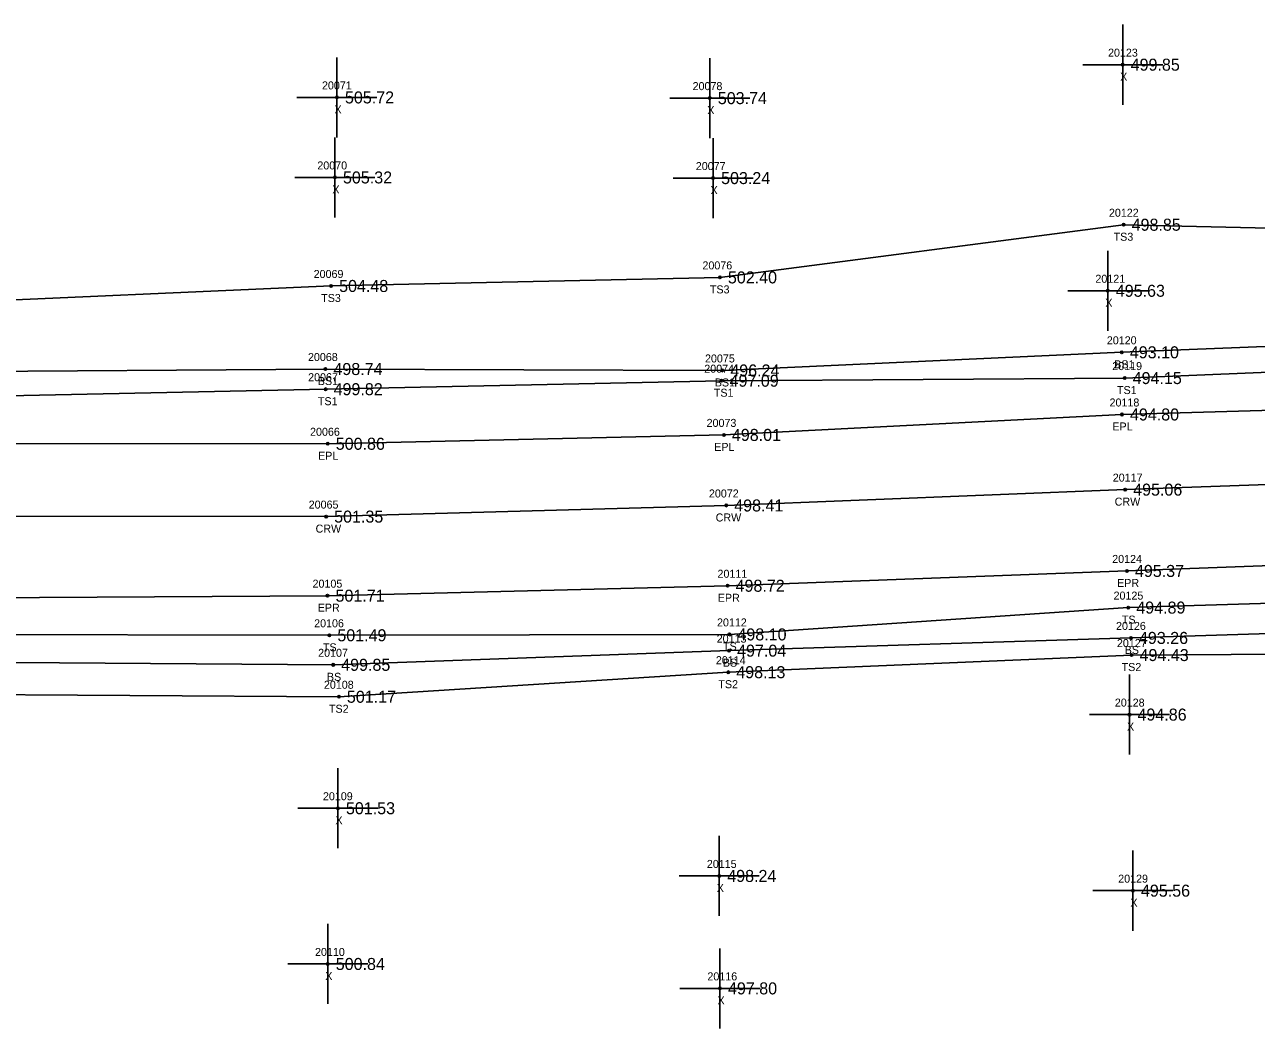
# Model space of a CAD drawing. Extents: x 1785066 to 1786589, y 770293 to 771312.
# Drawn here: x 1785243.3 to 1785397.2, y 770773.1 to 770898.5 of the extents above; entities that cross this region are included whole.
import ezdxf

# ---------------------------------------------------------------- set-up
doc = ezdxf.new("R2010")
doc.units = 0
for name, color, linetype in [('RD_DTM_BkLn1', 7, 'Continuous'), ('RD_DTM_BkLn2', 7, 'Continuous'), ('RD_DTM_BkLn_txCode', 7, 'Continuous'), ('RD_EX_Misc', 7, 'Continuous'), ('RD_EX_Misc_txCode', 7, 'Continuous'), ('RD_EX_Road', 7, 'Continuous'), ('RD_EX_Road_txCode', 7, 'Continuous'), ('RD_EX_TX_Misc_ELEV', 7, 'Continuous'), ('RD_EX_TX_Road_ELEV', 7, 'Continuous'), ('RD_HC_Survey_ELEV', 7, 'Continuous'), ('RD_HC_Survey_txCode', 7, 'Continuous'), ('RD_SMD_Locator', 7, 'Continuous')]:
    doc.layers.add(name, color=color, linetype=linetype)

msp = doc.modelspace()

# ---------------------------------------------------------------- linework, layer by layer
at = {"layer": 'RD_DTM_BkLn1'}
msp.add_lwpolyline([(1785082.06, 770851.29), (1785131.3, 770843.85), (1785181.17, 770839.05), (1785231.06, 770837.12), (1785280.99, 770837.06), (1785330.97, 770838.45), (1785380.81, 770840.43), (1785480.56, 770843.94), (1785580.22, 770847.33), (1785679.99, 770850.66), (1785779.91, 770853.54)], dxfattribs=at)
at = {"layer": 'RD_DTM_BkLn2'}
for points in [[(1785219, 770887.48), (1785221.61, 770869.17), (1785226.44, 770862.44), (1785230.83, 770863.64), (1785281.61, 770865.88), (1785330.18, 770866.95), (1785380.62, 770873.53), (1785481.03, 770871.22), (1785579.17, 770869.06), (1785678.49, 770873.66), (1785753.25, 770880.69), (1785777.57, 770887.66), (1785796.72, 770894.6)], [(1785221.18, 770856.06), (1785231.29, 770855.17), (1785280.9, 770855.5), (1785330.48, 770855.32), (1785380.39, 770857.59), (1785481.4, 770861.59), (1785579.34, 770865.13), (1785679.06, 770868.59), (1785753.94, 770876.35), (1785778.96, 770883.81)], [(1785221.33, 770857.68), (1785219.57, 770857.18), (1785219.95, 770853.94), (1785231.29, 770851.96), (1785280.92, 770852.98), (1785330.39, 770854.04), (1785380.75, 770854.37), (1785480.88, 770858.51), (1785579.51, 770861.16), (1785679.28, 770865.65), (1785754.2, 770872.9), (1785779.7, 770881.19), (1785786.95, 770881.8), (1785789.14, 770878.77), (1785786.05, 770869.32), (1785786.11, 770839.44)], [(1785205.07, 770819.03), (1785219.41, 770822.94), (1785230.95, 770822.33), (1785281.39, 770822.23), (1785331.37, 770822.34), (1785381.2, 770825.69), (1785481.76, 770828.75), (1785580.39, 770831.91), (1785680.81, 770834.37), (1785757.11, 770838.03), (1785775.28, 770836.8), (1785785.27, 770835.59), (1785786.11, 770839.44)], [(1785217.48, 770818.88), (1785230.53, 770818.92), (1785281.87, 770818.54), (1785331.33, 770820.31), (1785381.53, 770821.9), (1785481.77, 770825.03), (1785580.88, 770828.75), (1785679.45, 770830.28), (1785757.48, 770831.63), (1785774.02, 770829.34), (1785791.05, 770829.99), (1785795.95, 770830.77)], [(1785205.07, 770819.03), (1785218.74, 770813.87), (1785230.3, 770814.87), (1785282.58, 770814.55), (1785331.23, 770817.62), (1785381.61, 770819.76), (1785481.26, 770820.42), (1785579.63, 770825.21), (1785679.72, 770826.75), (1785756.33, 770825.6), (1785774.03, 770825.73), (1785791.3, 770827.72), (1785795.65, 770828.98)]]:
    msp.add_lwpolyline(points, dxfattribs=at)
at = {"layer": 'RD_EX_Misc'}
for p, q in [((1785380.5, 770888.53), (1785380.5, 770898.53)), ((1785282.34, 770884.44), (1785282.34, 770894.44)), ((1785328.92, 770884.35), (1785328.92, 770894.35)), ((1785375.5, 770893.53), (1785385.5, 770893.53)), ((1785277.34, 770889.44), (1785287.34, 770889.44)), ((1785323.92, 770889.35), (1785333.92, 770889.35)), ((1785282.09, 770874.44), (1785282.09, 770884.44)), ((1785329.33, 770874.36), (1785329.33, 770884.36)), ((1785277.09, 770879.44), (1785287.09, 770879.44)), ((1785324.33, 770879.36), (1785334.33, 770879.36)), ((1785378.64, 770860.28), (1785378.64, 770870.28)), ((1785373.64, 770865.28), (1785383.64, 770865.28)), ((1785381.35, 770807.32), (1785381.35, 770817.32)), ((1785376.35, 770812.32), (1785386.35, 770812.32)), ((1785282.46, 770795.62), (1785282.46, 770805.62)), ((1785277.46, 770800.62), (1785287.46, 770800.62)), ((1785330.1, 770787.16), (1785330.1, 770797.16)), ((1785381.78, 770785.32), (1785381.78, 770795.32)), ((1785325.1, 770792.16), (1785335.1, 770792.16)), ((1785376.78, 770790.32), (1785386.78, 770790.32)), ((1785281.19, 770776.16), (1785281.19, 770786.16)), ((1785330.19, 770773.11), (1785330.19, 770783.11)), ((1785276.19, 770781.16), (1785286.19, 770781.16)), ((1785325.19, 770778.11), (1785335.19, 770778.11))]:
    msp.add_line(p, q, dxfattribs=at)
at = {"layer": 'RD_EX_Road'}
for points in [[(1785083.87, 770860.72), (1785132.91, 770853.08), (1785181.89, 770848.53), (1785200.96, 770847.97), (1785215.21, 770848.13), (1785231.38, 770846.18), (1785281.19, 770846.16), (1785330.68, 770847.27), (1785380.41, 770849.82), (1785480.96, 770852.71), (1785580.09, 770856.45), (1785680.2, 770859.84), (1785779.71, 770863.4)], [(1785079.74, 770841.1), (1785077.36, 770829.81), (1785127.59, 770822.23), (1785177.27, 770813.99), (1785180.45, 770828), (1785230.74, 770826.87), (1785281.16, 770827.18), (1785331.14, 770828.42), (1785381.03, 770830.27), (1785481.34, 770833.99), (1785580.1, 770837.94), (1785680.6, 770840.57), (1785780.28, 770843.87)]]:
    msp.add_lwpolyline(points, dxfattribs=at)
at = {"layer": 'RD_SMD_Locator'}
for centre in [(1785380.5, 770893.53), (1785282.34, 770889.44), (1785328.92, 770889.35), (1785282.09, 770879.44), (1785329.33, 770879.36), (1785380.62, 770873.53), (1785330.18, 770866.95), (1785281.61, 770865.88), (1785378.64, 770865.28), (1785380.39, 770857.59), (1785280.9, 770855.5), (1785330.48, 770855.32), (1785380.75, 770854.37), (1785280.92, 770852.98), (1785330.39, 770854.04), (1785380.41, 770849.82), (1785330.68, 770847.27), (1785281.19, 770846.16), (1785380.81, 770840.43), (1785330.97, 770838.45), (1785280.99, 770837.06), (1785381.03, 770830.27), (1785331.14, 770828.42), (1785281.16, 770827.18), (1785381.2, 770825.69), (1785281.39, 770822.23), (1785331.37, 770822.34), (1785381.53, 770821.9), (1785331.33, 770820.31), (1785381.61, 770819.76), (1785281.87, 770818.54), (1785331.23, 770817.62), (1785282.58, 770814.55), (1785381.35, 770812.32), (1785282.46, 770800.62), (1785330.1, 770792.16), (1785381.78, 770790.32), (1785281.19, 770781.16), (1785330.19, 770778.11)]:
    msp.add_circle(centre, 0.15, dxfattribs=at)

# ---------------------------------------------------------------- texts
at = {"layer": 'RD_DTM_BkLn_txCode'}
for s, p in [('20122', (1785378.78, 770874.53)), ('TS3', (1785379.37, 770871.53)), ('20076', (1785328, 770867.95)), ('20069', (1785279.43, 770866.88)), ('TS3', (1785328.93, 770864.95)), ('TS3', (1785280.37, 770863.88)), ('20120', (1785378.52, 770858.59)), ('20068', (1785278.72, 770856.5)), ('20074', (1785328.23, 770855.04)), ('20075', (1785328.32, 770856.32)), ('20119', (1785379.2, 770855.37)), ('BS1', (1785379.44, 770855.59)), ('20067', (1785278.74, 770853.98)), ('BS1', (1785279.95, 770853.5)), ('TS1', (1785329.42, 770852.04)), ('BS1', (1785329.54, 770853.32)), ('TS1', (1785379.79, 770852.37)), ('TS1', (1785279.96, 770850.98)), ('20125', (1785379.36, 770826.69)), ('20106', (1785279.49, 770823.23)), ('20112', (1785329.82, 770823.34)), ('20126', (1785379.67, 770822.9)), ('TS', (1785380.4, 770823.69)), ('20113', (1785329.78, 770821.31)), ('TS', (1785280.59, 770820.23)), ('TS', (1785330.57, 770820.34)), ('20127', (1785379.78, 770820.76)), ('BS', (1785380.75, 770819.9)), ('20107', (1785279.99, 770819.54)), ('20114', (1785329.68, 770818.62)), ('BS', (1785330.55, 770818.31)), ('BS', (1785281.09, 770816.54)), ('TS2', (1785380.37, 770817.76)), ('20108', (1785280.71, 770815.55)), ('TS2', (1785329.99, 770815.62)), ('TS2', (1785281.34, 770812.55))]:
    msp.add_text(s, height=1, dxfattribs=at).set_placement(p)
at = {"layer": 'RD_EX_Misc_txCode'}
for s, p in [('20123', (1785378.67, 770894.53)), ('20071', (1785280.47, 770890.44)), ('X', (1785380.19, 770891.53)), ('20078', (1785326.77, 770890.35)), ('X', (1785282.03, 770887.44)), ('X', (1785328.61, 770887.35)), ('20070', (1785279.89, 770880.44)), ('20077', (1785327.17, 770880.36)), ('X', (1785281.77, 770877.44)), ('X', (1785329.01, 770877.36)), ('20121', (1785377.09, 770866.28)), ('X', (1785378.33, 770863.28)), ('20128', (1785379.52, 770813.32)), ('X', (1785381.04, 770810.32)), ('20109', (1785280.59, 770801.62)), ('X', (1785282.15, 770798.62)), ('20115', (1785328.55, 770793.16)), ('20129', (1785379.94, 770791.32)), ('X', (1785329.79, 770790.16)), ('X', (1785381.46, 770788.32)), ('20110', (1785279.6, 770782.16)), ('X', (1785280.88, 770779.16)), ('20116', (1785328.62, 770779.11)), ('X', (1785329.88, 770776.11))]:
    msp.add_text(s, height=1, dxfattribs=at).set_placement(p)
at = {"layer": 'RD_EX_Road_txCode'}
for s, p in [('20118', (1785378.86, 770850.82)), ('20073', (1785328.52, 770848.27)), ('EPL', (1785379.21, 770847.82)), ('20066', (1785278.98, 770847.16)), ('EPL', (1785329.47, 770845.27)), ('EPL', (1785279.98, 770844.16)), ('20124', (1785379.19, 770831.27)), ('20111', (1785329.88, 770829.42)), ('20105', (1785279.29, 770828.18)), ('EPR', (1785379.8, 770828.27)), ('EPR', (1785329.92, 770826.42)), ('EPR', (1785279.94, 770825.18))]:
    msp.add_text(s, height=1, dxfattribs=at).set_placement(p)
at = {"layer": 'RD_EX_TX_Misc_ELEV'}
for s, p in [('499.85', (1785381.5, 770892.78)), ('505.72', (1785283.34, 770888.69)), ('503.74', (1785329.92, 770888.6)), ('505.32', (1785283.09, 770878.69)), ('503.24', (1785330.33, 770878.61)), ('498.85', (1785381.62, 770872.78)), ('502.40', (1785331.18, 770866.2)), ('504.48', (1785282.61, 770865.13)), ('495.63', (1785379.64, 770864.53)), ('493.10', (1785381.39, 770856.84)), ('498.74', (1785281.9, 770854.75)), ('496.24', (1785331.48, 770854.57)), ('497.09', (1785331.39, 770853.29)), ('494.15', (1785381.75, 770853.62)), ('499.82', (1785281.92, 770852.23)), ('494.89', (1785382.2, 770824.94)), ('501.49', (1785282.39, 770821.48)), ('498.10', (1785332.37, 770821.59)), ('493.26', (1785382.53, 770821.15)), ('497.04', (1785332.33, 770819.56)), ('499.85', (1785282.87, 770817.79)), ('494.43', (1785382.61, 770819.01)), ('498.13', (1785332.23, 770816.87)), ('501.17', (1785283.58, 770813.8)), ('494.86', (1785382.35, 770811.57)), ('501.53', (1785283.46, 770799.87)), ('498.24', (1785331.1, 770791.41)), ('495.56', (1785382.78, 770789.57)), ('500.84', (1785282.19, 770780.41)), ('497.80', (1785331.19, 770777.36))]:
    msp.add_text(s, height=1.5, dxfattribs=at).set_placement(p)
at = {"layer": 'RD_EX_TX_Road_ELEV'}
for s, p in [('494.80', (1785381.41, 770849.07)), ('500.86', (1785282.19, 770845.41)), ('498.01', (1785331.68, 770846.52)), ('495.37', (1785382.03, 770829.52)), ('498.72', (1785332.14, 770827.67)), ('501.71', (1785282.16, 770826.43))]:
    msp.add_text(s, height=1.5, dxfattribs=at).set_placement(p)
at = {"layer": 'RD_HC_Survey_ELEV'}
for s, p in [('495.06', (1785381.81, 770839.68)), ('498.41', (1785331.97, 770837.7)), ('501.35', (1785281.99, 770836.31))]:
    msp.add_text(s, height=1.5, dxfattribs=at).set_placement(p)
at = {"layer": 'RD_HC_Survey_txCode'}
for s, p in [('20117', (1785379.26, 770841.43)), ('20065', (1785278.81, 770838.06)), ('20072', (1785328.81, 770839.45)), ('CRW', (1785379.5, 770838.43)), ('CRW', (1785279.67, 770835.06)), ('CRW', (1785329.65, 770836.45))]:
    msp.add_text(s, height=1, dxfattribs=at).set_placement(p)

doc.saveas('drawing.dxf')
